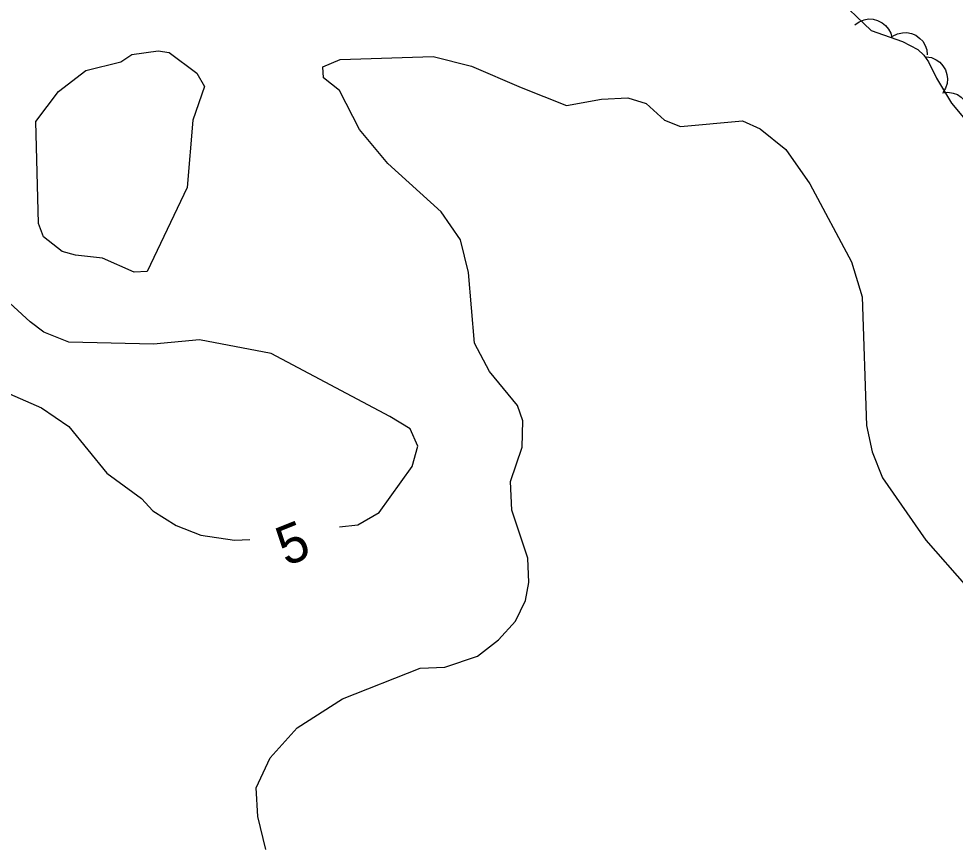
# Model space of a CAD drawing. Extents: x 336540 to 340074, y 5572036 to 5573747.
# Drawn here: x 336650.1 to 336721.6, y 5572550.3 to 5572613.7 of the extents above; entities that cross this region are included whole.
import ezdxf

# ---------------------------------------------------------------- set-up
doc = ezdxf.new("R2010")
doc.units = 0
for name, color, linetype in [('Niveau 1', 7, 'Continuous'), ('Niveau 2', 7, 'Continuous'), ('Niveau 44', 7, 'Continuous')]:
    doc.layers.add(name, color=color, linetype=linetype)

msp = doc.modelspace()

# ---------------------------------------------------------------- linework, layer by layer
at = {"layer": 'Niveau 1'}
for points in [[(336674.61, 5572574.88), (336676.01, 5572575.03), (336677.65, 5572575.96), (336680.17, 5572579.48), (336680.6, 5572581.03), (336680.02, 5572582.36), (336678.45, 5572583.29), (336669.4, 5572588.1), (336663.94, 5572589.16), (336660.41, 5572588.82), (336653.96, 5572588.98), (336652.05, 5572589.73), (336651.01, 5572590.52), (336648.17, 5572593.09)], [(336649.43, 5572585.02), (336651.86, 5572583.96), (336653.95, 5572582.54), (336656.84, 5572578.97), (336659.49, 5572577.05), (336660.37, 5572576.09), (336662.14, 5572574.99), (336664.03, 5572574.24), (336666.59, 5572573.87), (336667.76, 5572573.92)]]:
    msp.add_lwpolyline(points, dxfattribs=at)
at = {"layer": 'Niveau 2'}
for points in [[(336662.99, 5572600.8), (336659.94, 5572594.38), (336658.94, 5572594.33), (336656.52, 5572595.38), (336654.46, 5572595.63), (336653.44, 5572595.91), (336652.02, 5572597.03), (336651.63, 5572598.03), (336651.42, 5572605.82), (336653.15, 5572608.12), (336655.25, 5572609.73), (336657.93, 5572610.39), (336658.76, 5572610.94), (336660.78, 5572611.22), (336661.62, 5572611.09), (336663.73, 5572609.51), (336664.3, 5572608.51), (336663.42, 5572605.93), (336662.99, 5572600.8)], [(336676.14, 5572605.22), (336674.62, 5572608.2), (336673.39, 5572609.17), (336673.35, 5572610.01), (336674.68, 5572610.57), (336681.77, 5572610.78), (336684.69, 5572610.06), (336688.48, 5572608.42), (336691.94, 5572607.06), (336694.62, 5572607.54), (336696.64, 5572607.64), (336698.03, 5572607.2), (336699.44, 5572605.92), (336700.65, 5572605.45), (336705.38, 5572605.88), (336706.75, 5572605.27), (336708.7, 5572603.68), (336710.53, 5572601.06), (336713.71, 5572595.11), (336714.53, 5572592.44), (336714.86, 5572582.61), (336715.3, 5572580.6), (336716.09, 5572578.62), (336719.38, 5572573.86), (336725.66, 5572566.72)], [(336680.79, 5572564.08), (336682.65, 5572564.17), (336685.16, 5572564.99), (336686.77, 5572566.26), (336688.05, 5572567.68), (336688.83, 5572569.25), (336689.08, 5572570.62), (336689, 5572572.49), (336687.78, 5572576.14), (336687.67, 5572578.34), (336688.56, 5572580.95), (336688.62, 5572582.97), (336688.22, 5572584.14), (336686.06, 5572586.74), (336684.92, 5572588.89), (336684.48, 5572594.3), (336683.85, 5572596.8), (336682.38, 5572598.94), (336678.3, 5572602.63), (336676.14, 5572605.22)], [(336669, 5572550.25), (336668.37, 5572552.76), (336668.26, 5572554.95), (336669.33, 5572557.23), (336671.39, 5572559.52), (336674.84, 5572561.74), (336680.79, 5572564.08)]]:
    msp.add_lwpolyline(points, dxfattribs=at)
at = {"layer": 'Niveau 44'}
for points in [[(336672.16, 5572622.88), (336675.36, 5572622), (336678.87, 5572622.05), (336682.1, 5572621.21), (336687.09, 5572620.4), (336690.22, 5572619.31), (336693.51, 5572617.98), (336694.51, 5572616.77), (336695.53, 5572615.35), (336697.04, 5572614.98), (336698.8, 5572614.91), (336700.53, 5572615.03), (336703.9, 5572615.5), (336707.37, 5572615.5), (336710.67, 5572615.87), (336712.45, 5572615.44), (336715.21, 5572612.77), (336717.62, 5572611.93), (336718.77, 5572611.32), (336719.23, 5572610.9), (336719.6, 5572610.38), (336720.2, 5572609.14), (336721.34, 5572607.22), (336722.26, 5572606.13)], [(336713.97, 5572613.2), (336714.3, 5572613.45), (336714.68, 5572613.59), (336715.01, 5572613.66), (336715.36, 5572613.63), (336715.71, 5572613.54), (336716.05, 5572613.36), (336716.32, 5572613.17), (336716.53, 5572612.89), (336716.71, 5572612.56), (336716.8, 5572612.22)], [(336716.85, 5572612.34), (336717.22, 5572612.53), (336717.62, 5572612.61), (336717.95, 5572612.63), (336718.29, 5572612.55), (336718.63, 5572612.41), (336718.94, 5572612.17), (336719.17, 5572611.95), (336719.34, 5572611.64), (336719.46, 5572611.29), (336719.5, 5572610.93)], [(336719.41, 5572610.77), (336719.82, 5572610.71), (336720.19, 5572610.54), (336720.47, 5572610.36), (336720.7, 5572610.09), (336720.89, 5572609.77), (336721, 5572609.41), (336721.05, 5572609.08), (336721.01, 5572608.74), (336720.9, 5572608.38), (336720.72, 5572608.07)], [(336720.67, 5572608.02), (336721.08, 5572608.06), (336721.48, 5572607.99), (336721.8, 5572607.88), (336722.08, 5572607.68), (336722.35, 5572607.42), (336722.54, 5572607.09), (336722.68, 5572606.79), (336722.72, 5572606.44), (336722.7, 5572606.07), (336722.6, 5572605.72)]]:
    msp.add_lwpolyline(points, dxfattribs=at)

# ---------------------------------------------------------------- texts
at = {"layer": 'Niveau 1'}
msp.add_text('5', height=3, rotation=21.68906, dxfattribs=at).set_placement((336670.54, 5572571.84))

doc.saveas('drawing.dxf')
